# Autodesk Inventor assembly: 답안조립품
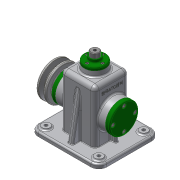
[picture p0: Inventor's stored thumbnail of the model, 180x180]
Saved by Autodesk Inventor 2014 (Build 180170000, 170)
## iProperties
Created: 2016-06
Part Number: 답안조립품
Document SubType Name: Assembly
Designer: user
Author: user
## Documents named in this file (19)
- C:\Users\user\Desktop\Manufacturing2급-임훈\답안조립품.iam
- C:\Users\user\Desktop\Manufacturing2급-임훈\본체.ipt
- C:\Users\user\Desktop\Manufacturing2급-임훈\뒤커버.ipt
- C:\Users\user\Desktop\Manufacturing2급-임훈\볼트 M4 x 10.ipt
- C:\Users\user\Desktop\Manufacturing2급-임훈\앞커버.ipt
- C:\Users\user\Desktop\Manufacturing2급-임훈\오일실 15 25 7.ipt
- C:\Users\user\Desktop\Manufacturing2급-임훈\베어링 15 x 35 x 11.ipt
- C:\Users\user\Desktop\Manufacturing2급-임훈\편심축.ipt
- C:\Users\user\Desktop\Manufacturing2급-임훈\멈춤링 15 x 1.ipt
- C:\Users\user\Desktop\Manufacturing2급-임훈\키 5 x 5 x 14.ipt
- C:\Users\user\Desktop\Manufacturing2급-임훈\V-벨트풀리.ipt
- C:\Users\user\Desktop\Manufacturing2급-임훈\와셔.ipt
- C:\Users\user\Desktop\Manufacturing2급-임훈\볼트 M6 x 12.ipt
- C:\Users\user\Desktop\Manufacturing2급-임훈\링크.ipt
- C:\Users\user\Desktop\Manufacturing2급-임훈\고정핀.ipt
- C:\Users\user\Desktop\Manufacturing2급-임훈\멈춤링 6 x 5.ipt
- C:\Users\user\Desktop\Manufacturing2급-임훈\슬라이드바.ipt
- C:\Users\user\Desktop\Manufacturing2급-임훈\상부부시.ipt
- C:\Users\user\Desktop\Manufacturing2급-임훈\볼트 M3 x 8.ipt
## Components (15 placed, 5 different names)
1. V-벨트풀리:1
2. ISO 4018 M6 x 12:1 — 각도:4, 각도:5
3. 고정핀:1 — 플러쉬:2
4. ISO 4762 M4 x 10:1
5. ISO 4762 M4 x 10:2
6. ISO 4762 M4 x 10:3
7. ISO 4762 M4 x 10:4
8. ISO 4762 M4 x 10:5
9. ISO 4762 M4 x 10:6
10. ISO 4762 M4 x 10:7
11. ISO 4762 M4 x 10:8
12. ISO 4762 M3 x 8:1
13. ISO 4762 M3 x 8:2
14. ISO 4762 M3 x 8:3
15. ISO 4762 M3 x 8:4
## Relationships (3: Angle 2, Flush 1)
- 각도:4 [Angle]: ISO 4018 M6 x 12:1
- 각도:5 [Angle]: ISO 4018 M6 x 12:1
- 플러쉬:2 [Flush]: 고정핀:1
